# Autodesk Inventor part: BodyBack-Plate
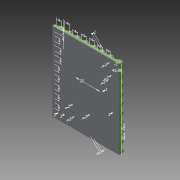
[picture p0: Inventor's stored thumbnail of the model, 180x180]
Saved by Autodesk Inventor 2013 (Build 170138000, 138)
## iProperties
Created: 2013-04
Part Number: BodyBack-Plate
Material: Generic
Document SubType Name: Modeling
Designer: frankenteddy
Density: 1 g/cm^3
Author: frankenteddy
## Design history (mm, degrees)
sketch "Sketch1"
  geometry: L1 (27.5, -9.689)-(27.5, -13.689); L2 (-4.099, 2.366)-(0, 4.733); L3 (-21.909, 32.5)-(-27.5, 32.5); L4 (-27.5, 26.909)-(-21.909, 32.5); L5 (-27.5, 24.081)-(-19.081, 32.5); L6 (-27.5, 24.081)-(-15.593, 24.081); L7 (-27.5, 20.081)-(-27.5, 24.081); L8 (-19.081, 32.5)-(-15.081, 32.5); L9 (-15.081, 32.5)-(-27.5, 20.081); L10 (-12.252, 32.5)-(-8.252, 32.5); L11 (-27.5, 17.252)-(-12.252, 32.5); L12 (-8.252, 32.5)-(-27.5, 13.252); L13 (-27.5, 10.424)-(-5.424, 32.5); L14 (-1.424, 32.5)-(-27.5, 6.424); L15 (-10, 5.774)-(0, 11.547); L16 (-27.5, 3.595)-(1.405, 32.5); L17 (-10, -5.774)-(-10, 5.774); L18 (5.405, 32.5)-(-27.5, -0.405); L19 (-27.5, -3.233)-(8.233, 32.5); L20 (-27.5, -10.061)-(15.061, 32.5); L21 (12.233, 32.5)-(-27.5, -7.233); L22 (-27.5, -0.405)-(-27.5, 3.595); L23 (10, -5.774)-(0, -11.547); L24 (-27.5, 17.252)-(-27.5, 13.252); L25 (-27.5, 10.424)-(-27.5, 6.424); L26 (-5.424, 32.5)-(-1.424, 32.5); L27 (-27.5, 32.5)-(-27.5, 26.909); L28 (15.061, 32.5)-(19.061, 32.5); L29 (27.5, 31.282)-(27.5, 27.282); L30 (21.89, 32.5)-(25.89, 32.5); L31 (8.233, 32.5)-(12.233, 32.5); L32 (27.5, 24.453)-(27.5, 20.453); L33 (1.405, 32.5)-(5.405, 32.5); L34 (27.5, 17.625)-(27.5, 13.625); L35 (19.061, 32.5)-(-4.475, 8.963); L36 (0.594, 11.204)-(21.89, 32.5); L37 (27.5, 10.796)-(27.5, 6.796); L38 (27.5, 20.453)-(10, 2.953); L39 (27.5, 3.968)-(27.5, -0.032); L40 (10, 0.125)-(27.5, 17.625); L41 (27.5, 13.625)-(10, -3.875); L42 (9.252, 6.205)-(27.5, 24.453); L43 (27.5, 27.282)-(7.459, 7.241); L44 (4.923, 8.705)-(27.5, 31.282); L45 (25.89, 32.5)-(3.13, 9.74); L46 (10, 5.774)-(10, -5.774); L47 (0, 11.547)-(10, 5.774); L48 (27.5, -2.86)-(27.5, -6.86); L49 (27.5, -16.517)-(27.5, -20.517); L50 (11.517, -32.5)-(27.5, -16.517); L51 (27.5, -13.689)-(8.689, -32.5); L52 (8.689, -32.5)-(4.689, -32.5); L53 (4.689, -32.5)-(27.5, -9.689); L54 (0, 4.733)-(4.099, 2.366); L55 (27.5, -6.86)-(1.86, -32.5); L56 (-2.14, -32.5)-(27.5, -2.86); L57 (27.5, -0.032)-(-4.968, -32.5); L58 (-8.968, -32.5)-(27.5, 3.968); L59 (-15.796, -32.5)-(27.5, 10.796); L60 (27.5, 6.796)-(-11.796, -32.5); L61 (27.5, -20.517)-(15.517, -32.5); L62 (15.517, -32.5)-(11.517, -32.5); L63 (18.346, -32.5)-(27.5, -23.346); L64 (22.346, -32.5)-(18.346, -32.5)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; C1 r 6.976 at (0, 0); 5 further points
  constraints: 186 end point, 59 parallel, 18 point on line, 17 perpendicular, 3 coincident, 1 centre point, 1 equal length, 1 horizontal, 1 vertical, 106 other
  dimensions: "d0" = 20 distance between parallel lines of L46 L17; "d1" = 45 deg angle of L6 L5; "d2" = 4 distance of L5.end L8.end; "d3" = 4 distance of L10.start L10.end; "d4" = 2 distance between parallel lines of L11 L9; "d5" = 4 distance of L13.end L14.start; "d6" = 2 distance between parallel lines of L13 L12; "d7" = 4 distance of L16.end L18.start; "d8" = 2 distance between parallel lines of L16 L14; "d9" = 4 distance of L19.end L21.start; "d10" = 2 distance between parallel lines of L19 L18; "d11" = 4 distance of L20.end L28.end; "d12" = 2 distance between parallel lines of L20 L21; "d13" = 4 distance of L30.start L30.end; "d14" = 4 distance of L29.start L29.end; "d15" = 4 distance of L84.end L80.start; "d16" = 2 distance between parallel lines of L79 L80; "d17" = 4 distance of L79.end L20.start; "d18" = 4 distance of L32.start L32.end; "d19" = 4 distance of L34.start L34.end; "d20" = 4 distance of L37.start L37.end; "d21" = 4 distance of L39.start L39.end; "d22" = 2 distance between parallel lines of L58 L60; "d23" = 4 distance of L48.start L48.end; "d24" = 2 distance between parallel lines of L56 L57; "d25" = 4 distance of L1.start L1.end; "d26" = 2 distance between parallel lines of L53 L55; "d27" = 4 distance of L49.start L49.end; "d28" = 2 distance between parallel lines of L50 L51; "d29" = 4 distance of L63.end L65.start; "d30" = 2 distance between parallel lines of L63 L61; "d31" = 2 distance between parallel lines of L67 L65; "d32" = 2 distance between parallel lines of L5 L4
sketch "Sketch2"
  geometry: L1 (-27.5, 32.5)-(27.5, 32.5); L2 (27.5, 32.5)-(27.5, -32.5); L3 (27.5, -32.5)-(-27.5, -32.5); L4 (-27.5, -32.5)-(-27.5, 32.5); 3 further points
  constraints: 8 end point, 2 midpoint, 2 parallel, 1 horizontal, 1 horizontal alignment, 1 perpendicular, 1 vertical alignment
  dimensions: "d33" = 55 distance of L2.end L3.end; "d34" = 65 distance of L1.end L2.end
extrude "Extrusion1" new body sketch "Sketch2" distance "d35" = 1.62; taper "d36" = 0 deg
extrude "Extrusion2" join sketch "Sketch1" distance "d37" = 2; taper "d38" = 0 deg
chamfer "Chamfer1" distance "d39" = 2; stored, may be unused: second distance "d40" = 2, angle "d41" = 45 deg
body "Solid1"
